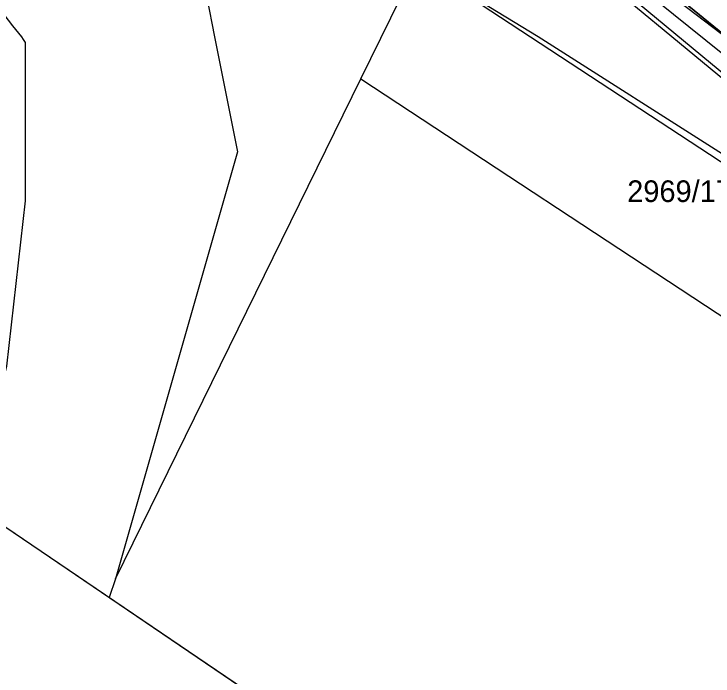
# Model space of a CAD drawing. Extents: x -621145 to -620023, y -1122866 to -1121971.
# Drawn here: x -620344.4 to -620295.98, y -1122770.39 to -1122724.49 of the extents above; entities that cross this region are included whole.
import ezdxf

# ---------------------------------------------------------------- set-up
doc = ezdxf.new("R2010")
doc.units = 0
for name, color, linetype in [('CETIN', 7, 'Continuous'), ('GasNet', 7, 'Continuous'), ('RÁMY', 7, 'Continuous'), ('SSZT-DK', 7, 'Continuous'), ('VAS vodovod', 7, 'Continuous'), ('Vrstva 53', 7, 'Continuous'), ('Vrstva 55', 7, 'Continuous'), ('Vrstva 57', 7, 'Continuous'), ('ČD-T', 7, 'Continuous')]:
    doc.layers.add(name, color=color, linetype=linetype)

msp = doc.modelspace()

# ---------------------------------------------------------------- linework, layer by layer
at = {"layer": 'CETIN'}
msp.add_lwpolyline([(-620402.98, -1122642.16), (-620362.48, -1122674.84), (-620281.95, -1122736.09)], dxfattribs=at)
at = {"layer": 'GasNet'}
msp.add_lwpolyline([(-620349.5, -1122710.44), (-620336.68, -1122702.48), (-620334.91, -1122701.4), (-620329.86, -1122698.6), (-620318.09, -1122706.99), (-620309.56, -1122715.75), (-620284.55, -1122735.89), (-620286.51, -1122738.72), (-620281.311, -1122742.821), (-620280.83, -1122743.2), (-620261.03, -1122754.43), (-620247.22, -1122761.95), (-620220.34, -1122775.27), (-620203.57, -1122783.96)], dxfattribs=at)
at = {"layer": 'RÁMY'}
for points in [[(-621061.558, -1122093.918), (-620106.075, -1122742.822), (-620189.505, -1122865.67), (-621144.989, -1122216.766)], [(-620887.834, -1122211.901), (-620106.075, -1122742.822), (-620189.505, -1122865.67), (-620971.264, -1122334.748)]]:
    msp.add_lwpolyline(points, close=True, dxfattribs=at)
at = {"layer": 'SSZT-DK'}
msp.add_lwpolyline([(-620359.04, -1122685.798), (-620308.772, -1122717.798), (-620291.405, -1122732.208), (-620277.196, -1122744.115), (-620257.608, -1122720.05), (-620250.251, -1122710.721), (-620233.29, -1122724.26), (-620218.699, -1122737.685), (-620210.438, -1122746.518), (-620193.319, -1122761.993), (-620178.352, -1122775.894), (-620171.184, -1122783.621), (-620164.843, -1122792.284), (-620156.695, -1122803.312), (-620151.985, -1122810.422)], dxfattribs=at)
at = {"layer": 'VAS vodovod'}
msp.add_lwpolyline([(-620347.512, -1122758.362), (-620346.67, -1122756.05), (-620345.785, -1122752.48), (-620344.9, -1122748.91), (-620344.25, -1122743.18), (-620343.6, -1122737.45), (-620343.605, -1122731.955), (-620343.61, -1122726.46), (-620343.74, -1122726.27), (-620343.87, -1122726.08), (-620344.48, -1122725.31), (-620345.09, -1122724.54), (-620345.76, -1122723.945), (-620346.43, -1122723.35), (-620346.441, -1122723.33), (-620346.48, -1122723.26), (-620346.53, -1122723.17), (-620346.655, -1122722.685), (-620346.78, -1122722.2)], dxfattribs=at)
at = {"layer": 'Vrstva 53'}
msp.add_line((-620278.65, -1122739.48), (-620307.94, -1122715.53), dxfattribs=at)
at = {"layer": 'Vrstva 55'}
for p, q in [((-620307.94, -1122715.53), (-620278.65, -1122739.48)), ((-620332.51, -1122716.01), (-620330.51, -1122726.08)), ((-620320.37, -1122729), (-620316.74, -1122721.6)), ((-620308.1, -1122726.09), (-620315.79, -1122721.36)), ((-620315.79, -1122721.36), (-620280.66, -1122744.45)), ((-620330.51, -1122726.08), (-620328.93, -1122734.05)), ((-620280.18, -1122743.84), (-620308.1, -1122726.09)), ((-620337.36, -1122763.66), (-620320.37, -1122729)), ((-620320.37, -1122729), (-620284.57, -1122752.56)), ((-620328.93, -1122734.05), (-620337.36, -1122763.66)), ((-620337.36, -1122763.66), (-620337.811, -1122764.951))]:
    msp.add_line(p, q, dxfattribs=at)
at = {"layer": 'ČD-T'}
msp.add_lwpolyline([(-620358.852, -1122685.564), (-620308.585, -1122717.564), (-620291.218, -1122731.973), (-620279.983, -1122741.462), (-620260.482, -1122717.473), (-620252.938, -1122708.192), (-620233.103, -1122724.025), (-620218.511, -1122737.45), (-620206.638, -1122747.527), (-620193.132, -1122761.758), (-620178.165, -1122775.66), (-620170.996, -1122783.386), (-620164.655, -1122792.049), (-620156.507, -1122803.078), (-620151.811, -1122810.167)], dxfattribs=at)

# ---------------------------------------------------------------- texts
at = {"layer": 'Vrstva 57'}
msp.add_text('2969/17', height=1.5, dxfattribs=at).set_placement((-620301.92, -1122737.53))

doc.saveas('drawing.dxf')
